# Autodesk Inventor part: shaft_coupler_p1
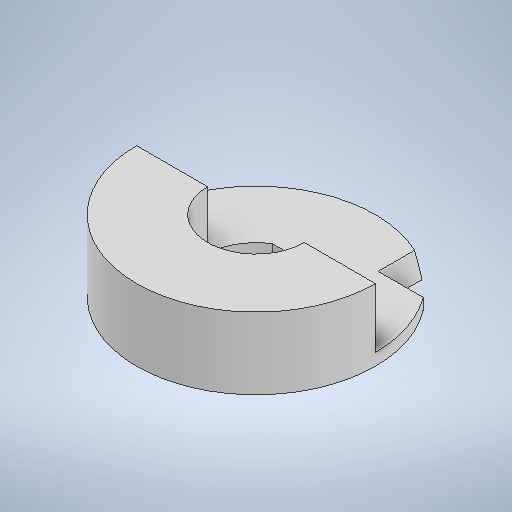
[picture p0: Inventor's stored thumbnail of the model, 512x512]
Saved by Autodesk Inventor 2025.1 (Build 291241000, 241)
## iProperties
Created: 2025-03
Part Number: shaft_coupler_p1
Material: Genérico
Document SubType Name: Modeling
Designer: Usuario
Density: 1 g/cm^3
Appearance: Valor por defecto
Author: Usuario
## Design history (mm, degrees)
sketch "Boceto1"
  geometry: L1 (-0.079, -4.178)-(-0.079, -3.578); L2 (-0.079, -3.578)-(2.2, -3.578); L3 (-0.079, -3.578)-(-2.2, -3.578); C1 r 10 at (0, 0); A1 r 4.2 centre (0, 0) between (2.2, -3.578) and (-2.2, -3.578); 1 further point
  constraints: 6 end point, 2 centre point, 2 coincident, 2 point on circle, 1 horizontal, 1 point on line, 1 vertical
  dimensions: "d0" = 8.4 diameter of A1; "d1" = 20 diameter of C1; "d2" = 0.6 distance of L1.start L1.end
extrude "Extrusión1" new body sketch "Boceto1" distance "d3" = 1; taper "d4" = 0 deg
node "Plano de trabajo1"
sketch "Boceto2"
  geometry: L1 (-4.05, 0)-(-10, 0); L2 (4.05, 0)-(10, 0); A1 r 10 centre (0, 0) between (-10, 0) and (10, 0); A2 r 4.05 centre (0, 0) between (-4.05, 0) and (4.05, 0); 3 further points
  constraints: 4 end point, 4 point on circle, 4 point on line, 2 centre point, 1 coincident
  dimensions: "d8" = 20 diameter of A1
extrude "Extrusión2" join sketch "Boceto2" distance "d6" = 5; taper "d7" = 0 deg
node "Plano de trabajo4"
sketch "Boceto3"
  geometry: L1 (0, 5.95)-(5, 5.95) reference; L2 (2.5, 5.95)-(2.5, 2.975); C1 r 1.5 at (2.5, 2.975); 1 further point
  constraints: 2 end point, 1 centre point, 1 coincident, 1 midpoint, 1 vertical
  dimensions: "d9" = 2.975 distance of L2.start L2.end; "d10" = 3 diameter of C1
extrude "screw" cut sketch "Boceto3" distance "d11" = 4; taper "d12" = 0 deg
feature "Rosca1" dims "d13" = 4, "d14" = 0
node "Plano de trabajo5"
sketch "Boceto4"
  geometry: C1 r 1.5 at (2.975, 2.5) reference; C2 r 3.75 at (2.975, 2.5); C3 r 1.5 at (2.975, 2.5); 1 further point
  constraints: 2 centre point, 2 coincident, 1 concentric
  dimensions: "d16" = 7.5 diameter of C2
extrude "Extrusión4" cut sketch "Boceto4" distance "d17" = 5; taper "d18" = 0 deg
node "Sólido1"
other parameters: "d5" = 0, "d15" = 6
